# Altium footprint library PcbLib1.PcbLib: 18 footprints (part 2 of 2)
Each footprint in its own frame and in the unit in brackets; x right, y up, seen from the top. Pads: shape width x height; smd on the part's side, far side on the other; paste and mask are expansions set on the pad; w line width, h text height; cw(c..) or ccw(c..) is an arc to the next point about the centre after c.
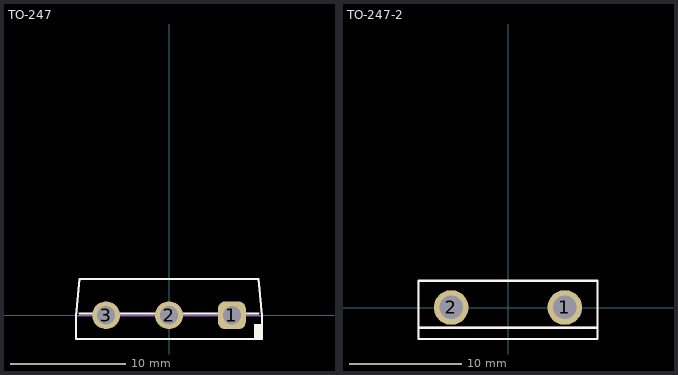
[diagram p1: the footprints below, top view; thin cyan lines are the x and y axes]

## TO-247 [mil]
pads (3):
  rrect50% 95x95 hole 62: 1(214,0)
  round 95 / inner round 74.8 / far side round 96 hole 62: 2(-1,0) 3(-216,0)
Top Overlay:
  region: 316.51,-30 289,-30 289,-81.11 316.51,-81.11
  lines w7: -307.3,6.01 305.63,6.01 ; -318.53,-81.11 -318.53,-2.37 -307.47,124.01 305.45,124.01 316.51,-2.37 316.51,-81.11 -318.53,-81.11
Bottom Overlay:
  circle w8.27: c-0.98,700.79 r70.87
  lines w3.94: -314.96,196.85 -314.96,944.88 314.96,944.88 314.96,196.85
Mechanical 5:
  lines w5: -307.3,6.01 305.63,6.01 ; -318.53,-2.37 -307.47,124.01 305.45,124.01 316.51,-2.37 ; -318.53,-2.37 -318.53,-81.11 316.51,-81.11 316.51,-2.37 ; -318.53,-2.37 316.51,-2.37
  text ".Designator" at 77.74,78.74 h40
3D body "TO-274.stp": height 1007.29, standoff -623.42, extent -318.53,-81.11 316.51,124.01

## TO-247-2 [mm] "TH, 2-Leads, Body 15.75x4.95mm, Pin Spacing 10.16mm"
height 24.51
pads (2):
  round 3.1 hole 2.1: 1(5.08,0.007) 2(-5.08,0.007)
Top Overlay:
  lines w0.2: -8.005,-1.803 8.005,-1.803 ; -8.005,-2.808 8.005,-2.808 8.005,2.402 -8.005,2.402 -8.005,-2.808
Bottom Overlay:
  circle w0.1: c0,17.8 r1.8
  lines w0.1: -8,5 -8,24 8,24 8,5
Mechanical 6:
  lines w0.1: -8.005,-1.703 8.005,-1.703 ; -8.005,-2.808 8.005,-2.808 8.005,2.402 -8.005,2.402 -8.005,-2.808
3D body "TO-247.step": height 23.77, standoff -2.21, extent -8.005,-2.808 8.004,2.402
